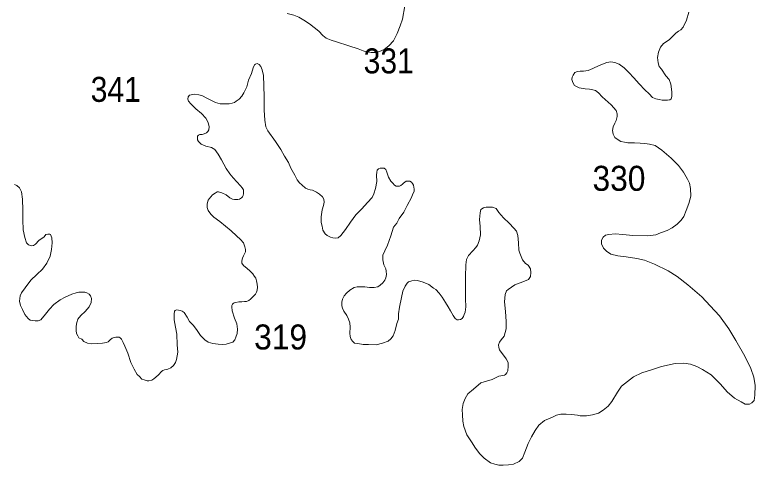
# Model space of a CAD drawing. Extents: x 445.4 to 500, y 8728.7 to 8784.
# Drawn here: x 467.934 to 472.675, y 8746.885 to 8749.766 of the extents above; entities that cross this region are included whole.
import ezdxf

# ---------------------------------------------------------------- set-up
doc = ezdxf.new("R2010")
doc.units = 0
doc.header["$LTSCALE"] = 0.064
doc.layers.add('2', color=7, linetype='Continuous', lineweight=13)
doc.layers.add('21', color=7, linetype='Continuous')

msp = doc.modelspace()

# ---------------------------------------------------------------- linework, layer by layer
at = {"layer": '2'}
for points in [[(470.4322, 8749.824), (470.4166, 8749.7394), (470.4024, 8749.6969), (470.3825, 8749.6459), (470.3584, 8749.5991), (470.33, 8749.5679), (470.2988, 8749.5439), (470.2689, 8749.5311), (470.242, 8749.5254), (470.2307, 8749.5259), (470.2165, 8749.5264), (470.2047, 8749.5278), (470.1859, 8749.5302), (470.1656, 8749.5358), (470.1321, 8749.5481), (470.0726, 8749.5674), (469.9943, 8749.5929), (469.9588, 8749.6042), (469.9276, 8749.617), (469.9063, 8749.634), (469.8807, 8749.6609), (469.8211, 8749.7077), (469.7852, 8749.7324), (469.7525, 8749.7508), (469.7199, 8749.7636), (469.6787, 8749.7749)], [(471.6363, 8749.4234), (471.6761, 8749.4432), (471.7258, 8749.4617), (471.7513, 8749.4659), (471.7769, 8749.4617), (471.8038, 8749.4503), (471.8365, 8749.4277), (471.8663, 8749.3979), (471.8975, 8749.3625), (471.9316, 8749.3256), (471.9685, 8749.2874), (471.9969, 8749.2604), (472.0182, 8749.2378), (472.0395, 8749.2293), (472.0608, 8749.2236), (472.0793, 8749.2208), (472.102, 8749.2194), (472.1134, 8749.2194), (472.1276, 8749.2222), (472.1361, 8749.2293), (472.1417, 8749.2434), (472.1417, 8749.2732), (472.1347, 8749.3228), (472.1247, 8749.3526), (472.102, 8749.3766), (472.075, 8749.4192), (472.0608, 8749.4362), (472.0537, 8749.4588), (472.0485, 8749.4937), (472.0556, 8749.5277), (472.0684, 8749.5589), (472.0869, 8749.583), (472.1238, 8749.607), (472.1437, 8749.6255), (472.1593, 8749.6411), (472.1678, 8749.6481), (472.1834, 8749.6609), (472.199, 8749.6708), (472.2146, 8749.6864), (472.2345, 8749.7332), (472.2505, 8749.7838)], [(469.1299, 8749.1353), (469.0939, 8749.1646), (469.06, 8749.1968), (469.0465, 8749.2137), (469.0408, 8749.2272), (469.0442, 8749.2407), (469.0532, 8749.2519), (469.0837, 8749.2587), (469.113, 8749.2553), (469.1355, 8749.2474), (469.1637, 8749.2339), (469.2179, 8749.2058), (469.2494, 8749.1979), (469.2742, 8749.1968), (469.3058, 8749.1979), (469.3261, 8749.2002), (469.3408, 8749.2058), (469.3521, 8749.2137), (469.3701, 8749.2272), (469.3881, 8749.2452), (469.4005, 8749.2677), (469.4186, 8749.306), (469.431, 8749.3476), (469.4495, 8749.392), (469.4608, 8749.428), (469.4687, 8749.4472), (469.4743, 8749.4517), (469.4867, 8749.4539), (469.498, 8749.4483), (469.5093, 8749.4348), (469.5172, 8749.4145), (469.5262, 8749.3785), (469.5284, 8749.3121), (469.5307, 8749.2423), (469.5308, 8749.1561), (469.5353, 8749.092), (469.5421, 8749.0492), (469.5545, 8749.0245), (469.6042, 8748.955), (469.6369, 8748.9044), (469.6605, 8748.8627), (469.6865, 8748.8222), (469.7011, 8748.7862), (469.7279, 8748.7402), (469.7412, 8748.7111), (469.7571, 8748.692), (469.7712, 8748.6787), (469.7954, 8748.6571), (469.8104, 8748.6513), (469.8245, 8748.6463), (469.8403, 8748.6455), (469.8662, 8748.6322), (469.8845, 8748.6189), (469.9036, 8748.6014), (469.9134, 8748.5871), (469.9149, 8748.5671), (469.9103, 8748.5456), (469.9026, 8748.5179), (469.8964, 8748.4749), (469.8964, 8748.438), (469.901, 8748.4134), (469.9072, 8748.3888), (469.9211, 8748.3657), (469.9349, 8748.3534), (469.955, 8748.3442), (469.9704, 8748.3396), (469.9873, 8748.3365), (470.0043, 8748.3396), (470.0212, 8748.3549), (470.0505, 8748.3918), (470.0828, 8748.4395), (470.1183, 8748.4856), (470.1552, 8748.5256), (470.1922, 8748.5656), (470.2215, 8748.5979), (470.2338, 8748.6209), (470.2446, 8748.6548), (470.2523, 8748.6994), (470.2494, 8748.7404), (470.2513, 8748.7595), (470.2552, 8748.7719), (470.2628, 8748.7814), (470.2742, 8748.7852), (470.2876, 8748.7862), (470.2981, 8748.7842), (470.3096, 8748.7776), (470.3172, 8748.7604), (470.3277, 8748.728), (470.342, 8748.7023), (470.3554, 8748.6889), (470.3659, 8748.6766), (470.3764, 8748.6708), (470.3888, 8748.6699), (470.3974, 8748.6708), (470.406, 8748.6746), (470.4156, 8748.6823), (470.4223, 8748.6899), (470.4308, 8748.6966), (470.4404, 8748.7013), (470.4509, 8748.7023), (470.4633, 8748.7013)], [(472.0106, 8747.4958), (472.0757, 8747.5166), (472.1616, 8747.5345), (472.2185, 8747.5373), (472.2614, 8747.5304), (472.3016, 8747.5166), (472.3376, 8747.4972), (472.3924, 8747.4625), (472.4534, 8747.403), (472.495, 8747.3546), (472.5435, 8747.3145), (472.5851, 8747.2896), (472.6114, 8747.2758), (472.628, 8747.2744), (472.6391, 8747.2758), (472.6544, 8747.2841), (472.6682, 8747.2993), (472.6724, 8747.3325), (472.6751, 8747.3947), (472.6654, 8747.4487), (472.6474, 8747.5026), (472.6086, 8747.5828), (472.5506, 8747.6821), (472.5063, 8747.7568), (472.4467, 8747.8397), (472.3871, 8747.9034), (472.3343, 8747.961), (472.2442, 8748.0384), (472.1749, 8748.0923), (472.1181, 8748.1283), (472.0303, 8748.1719), (471.9652, 8748.1968), (471.9167, 8748.2064), (471.8487, 8748.2189), (471.7961, 8748.2244), (471.7504, 8748.2355), (471.7226, 8748.2535), (471.7032, 8748.2728), (471.6908, 8748.3005), (471.6908, 8748.324), (471.7005, 8748.3434), (471.7157, 8748.3558), (471.7379, 8748.36), (471.7781, 8748.3641), (471.8266, 8748.36), (471.8917, 8748.3544), (471.9859, 8748.3517), (472.0386, 8748.3586), (472.0677, 8748.371), (472.1107, 8748.3862), (472.1442, 8748.4037), (472.1747, 8748.4273), (472.201, 8748.4522), (472.2177, 8748.4757), (472.2329, 8748.5144), (472.2509, 8748.56), (472.262, 8748.6057), (472.2607, 8748.6549), (472.2538, 8748.6895), (472.2413, 8748.7157), (472.2163, 8748.76), (472.1831, 8748.8015), (472.136, 8748.8499), (472.0764, 8748.8997), (472.0345, 8748.9296), (471.9985, 8748.9393), (471.968, 8748.9435), (471.9389, 8748.9462), (471.9023, 8748.9464), (471.8597, 8748.9464), (471.8384, 8748.9506), (471.8157, 8748.9563), (471.7973, 8748.9662), (471.776, 8748.9818), (471.766, 8749.003), (471.7618, 8749.0271), (471.7646, 8749.0498), (471.776, 8749.0725), (471.7845, 8749.0895), (471.7902, 8749.115), (471.7902, 8749.1334), (471.7845, 8749.1547), (471.7532, 8749.1901), (471.6959, 8749.242), (471.6718, 8749.2675), (471.6533, 8749.2817), (471.6363, 8749.2874), (471.6136, 8749.2902), (471.5866, 8749.293), (471.5483, 8749.3001), (471.5185, 8749.3143), (471.5071, 8749.3327), (471.5014, 8749.3526), (471.5028, 8749.3667), (471.5099, 8749.3809), (471.5199, 8749.3979), (471.5369, 8749.4036), (471.554, 8749.405), (471.5753, 8749.4064), (471.6065, 8749.4107), (471.6363, 8749.4234)], [(469.2612, 8747.6567), (469.2876, 8747.6598), (469.3079, 8747.666), (469.3297, 8747.6722), (469.3437, 8747.6862), (469.3484, 8747.7033), (469.3577, 8747.7282), (469.3593, 8747.7561), (469.3546, 8747.7888), (469.3406, 8747.8261), (469.3266, 8747.8727), (469.3226, 8747.8971), (469.3226, 8747.9067), (469.3271, 8747.9142), (469.3316, 8747.9187), (469.3383, 8747.9231), (469.3487, 8747.9261), (469.3682, 8747.9298), (469.3883, 8747.9306), (469.404, 8747.9313), (469.4174, 8747.9328), (469.4316, 8747.9388), (469.4428, 8747.9462), (469.4547, 8747.9574), (469.4644, 8747.9686), (469.4741, 8747.9797), (469.4808, 8747.9924), (469.4861, 8748.0051), (469.4876, 8748.0237), (469.4861, 8748.0438), (469.4808, 8748.0646), (469.4773, 8748.0808), (469.4691, 8748.0927), (469.4572, 8748.1091), (469.4408, 8748.127), (469.4191, 8748.1449), (469.4012, 8748.1612), (469.3915, 8748.1702), (469.3885, 8748.1784), (469.3885, 8748.1888), (469.39, 8748.2022), (469.3923, 8748.2104), (469.3982, 8748.2253), (469.4101, 8748.2494), (469.4112, 8748.2641), (469.4078, 8748.2809), (469.3977, 8748.3068), (469.3796, 8748.3282), (469.3537, 8748.353), (469.3187, 8748.3834), (469.2466, 8748.4441), (469.2091, 8748.4707), (469.1888, 8748.491), (469.1719, 8748.5135), (469.1662, 8748.5338), (469.1662, 8748.5563), (469.1719, 8748.5799), (469.1786, 8748.59), (469.1888, 8748.6013), (469.2001, 8748.6148), (469.217, 8748.6261), (469.2305, 8748.6328), (469.2373, 8748.6328), (469.2587, 8748.6272), (469.2869, 8748.6137), (469.3106, 8748.5957), (469.3275, 8748.5878), (469.341, 8748.5844), (469.3624, 8748.5844), (469.3737, 8748.5878), (469.3861, 8748.5946), (469.3918, 8748.6013), (469.3963, 8748.6114), (469.3985, 8748.6227), (469.3985, 8748.6362), (469.3974, 8748.6475), (469.3906, 8748.6587), (469.3794, 8748.6722), (469.3321, 8748.7225), (469.3107, 8748.7496), (469.2881, 8748.7822), (469.2566, 8748.8385), (469.2363, 8748.8756), (469.2137, 8748.9037), (469.1923, 8748.9173), (469.1573, 8748.9263), (469.1266, 8748.9384), (469.1108, 8748.9552), (469.104, 8748.9665), (469.104, 8748.989), (469.1108, 8748.9969), (469.1187, 8749.0003), (469.1333, 8749.0014), (469.1457, 8749.0048), (469.1615, 8749.0115), (469.1705, 8749.0194), (469.1773, 8749.0307), (469.1784, 8749.0487), (469.1728, 8749.0768), (469.157, 8749.1061), (469.1299, 8749.1353)], [(470.4633, 8748.7013), (470.4748, 8748.6956), (470.4815, 8748.6861), (470.4872, 8748.6756), (470.49, 8748.6632), (470.491, 8748.6508), (470.491, 8748.6365), (470.4824, 8748.6213), (470.4738, 8748.5975), (470.4473, 8748.5455), (470.4243, 8748.5045), (470.3957, 8748.4626), (470.3795, 8748.433), (470.3584, 8748.4077), (470.3416, 8748.352), (470.3212, 8748.2925), (470.3025, 8748.2553), (470.2914, 8748.2293), (470.2914, 8748.1977), (470.297, 8748.1661), (470.31, 8748.142), (470.3118, 8748.1261), (470.3147, 8748.1049), (470.3099, 8748.0845), (470.3041, 8748.0681), (470.2915, 8748.0507), (470.273, 8748.0361), (470.2585, 8748.0255), (470.2343, 8748.0216), (470.2052, 8748.0226), (470.1761, 8748.0255), (470.1489, 8748.0265), (470.1257, 8748.0265), (470.1063, 8748.0207), (470.0791, 8748.0042), (470.0578, 8747.9848), (470.0432, 8747.9674), (470.0326, 8747.9481), (470.0287, 8747.9287), (470.0287, 8747.9045), (470.0318, 8747.8884), (470.0415, 8747.87), (470.0609, 8747.8429), (470.0716, 8747.8197), (470.0784, 8747.7955), (470.0803, 8747.7684), (470.0784, 8747.7287), (470.0813, 8747.7071), (470.0881, 8747.6887), (470.0978, 8747.6771), (470.1084, 8747.6665), (470.1298, 8747.6626), (470.1647, 8747.6568), (470.1986, 8747.6568), (470.2471, 8747.6558), (470.2878, 8747.6665), (470.3237, 8747.6791), (470.3421, 8747.6936), (470.3557, 8747.7129), (470.3693, 8747.7468), (470.3809, 8747.7923), (470.3906, 8747.8184), (470.3916, 8747.8533), (470.3964, 8747.8968), (470.4093, 8747.9576), (470.419, 8747.9992), (470.4336, 8748.0292), (470.4462, 8748.0486), (470.4559, 8748.0583), (470.4753, 8748.065), (470.4908, 8748.0679), (470.5102, 8748.067), (470.5267, 8748.0621), (470.548, 8748.0554), (470.5848, 8748.0399), (470.6149, 8748.0176), (470.6304, 8748.0079), (470.6517, 8747.9857), (470.6702, 8747.9595), (470.6925, 8747.9257), (470.7099, 8747.8986), (470.7235, 8747.8734), (470.7404, 8747.8428), (470.7539, 8747.8225), (470.7665, 8747.8148), (470.7753, 8747.8138), (470.7888, 8747.8167), (470.7976, 8747.8235), (470.8063, 8747.837), (470.8121, 8747.8486), (470.817, 8747.8631), (470.8218, 8747.899), (470.8208, 8747.9502), (470.82, 8748.0891), (470.8215, 8748.1662), (470.8256, 8748.2009), (470.8399, 8748.2254), (470.8665, 8748.2561), (470.887, 8748.2785), (470.8972, 8748.2928), (470.9074, 8748.3194)], [(467.9321, 8748.6801), (467.947, 8748.6742), (467.9634, 8748.6593), (467.9769, 8748.6339), (467.9828, 8748.5863), (467.9846, 8748.5168), (467.9846, 8748.4549), (467.9877, 8748.3915), (467.997, 8748.3421), (468.0094, 8748.308), (468.0218, 8748.2957), (468.0388, 8748.2879), (468.0528, 8748.2895), (468.0667, 8748.2988), (468.0869, 8748.322), (468.1209, 8748.3467), (468.1318, 8748.3606), (468.1442, 8748.3637), (468.1581, 8748.3637), (468.1628, 8748.3606), (468.1705, 8748.3405), (468.1736, 8748.3065), (468.169, 8748.2647), (468.1612, 8748.2215), (468.138, 8748.177), (468.1116, 8748.1383), (468.0745, 8748.1043), (468.0357, 8748.0687)], [(470.9074, 8748.3194), (470.916, 8748.3594), (470.9147, 8748.4119), (470.9105, 8748.4562), (470.9133, 8748.4991), (470.9188, 8748.5212), (470.9354, 8748.5323), (470.9521, 8748.535), (470.9742, 8748.5364), (470.9936, 8748.535), (471.0158, 8748.5267), (471.0324, 8748.5018), (471.0643, 8748.4672), (471.099, 8748.4327), (471.1294, 8748.4009), (471.1461, 8748.3815), (471.1558, 8748.3538), (471.1585, 8748.3082), (471.1613, 8748.2612), (471.1686, 8748.2411), (471.1853, 8748.1996), (471.2033, 8748.1761), (471.2213, 8748.1636), (471.2352, 8748.1415), (471.2393, 8748.1166), (471.2365, 8748.0931), (471.2227, 8748.0737), (471.1866, 8748.0585), (471.1368, 8748.0378), (471.0924, 8748.0087), (471.0826, 8747.9996), (471.0729, 8747.9775), (471.0702, 8747.9291), (471.0757, 8747.8682), (471.0813, 8747.8046), (471.0798, 8747.7582), (471.0743, 8747.7347), (471.0674, 8747.7112), (471.048, 8747.6863), (471.0369, 8747.6724), (471.0313, 8747.6558), (471.0327, 8747.6379), (471.0383, 8747.6226), (471.048, 8747.6088), (471.0632, 8747.5881), (471.0798, 8747.5645), (471.0923, 8747.5424), (471.0937, 8747.5175), (471.0909, 8747.4878), (471.0854, 8747.4754), (471.0771, 8747.4643), (471.0701, 8747.4602), (471.0327, 8747.4533), (470.9898, 8747.4339), (470.9191, 8747.4118), (470.8706, 8747.3717), (470.8359, 8747.3412), (470.8177, 8747.3116), (470.8052, 8747.2784), (470.7983, 8747.241), (470.7997, 8747.2078), (470.8024, 8747.1663), (470.8093, 8747.1323), (470.8287, 8747.0798), (470.8578, 8747.0341), (470.8841, 8746.9926), (470.9119, 8746.9581), (470.9396, 8746.929), (470.9811, 8746.9), (471.0075, 8746.8917), (471.0338, 8746.8848), (471.0601, 8746.8848), (471.0948, 8746.8861), (471.128, 8746.8917), (471.1641, 8746.9083), (471.1849, 8746.9304), (471.2001, 8746.9677), (471.2209, 8747.0244), (471.2417, 8747.0659), (471.2666, 8747.1074), (471.2888, 8747.1406), (471.3262, 8747.1697), (471.3775, 8747.1918), (471.4018, 8747.2058), (471.4295, 8747.2113), (471.4656, 8747.2113), (471.4988, 8747.2085), (471.5362, 8747.2044), (471.5542, 8747.2002), (471.5958, 8747.2016), (471.6332, 8747.2071), (471.6707, 8747.2182), (471.7025, 8747.2362), (471.733, 8747.2625), (471.7566, 8747.2915), (471.793, 8747.352), (471.8193, 8747.3893), (471.8568, 8747.4211), (471.8956, 8747.4502), (471.9496, 8747.4765), (472.0106, 8747.4958)], [(468.0357, 8748.0687), (468.0001, 8748.0193), (467.9769, 8747.9883), (467.9676, 8747.9682), (467.9645, 8747.9342), (467.9707, 8747.9064), (467.9831, 8747.8801), (467.9986, 8747.8492), (468.0188, 8747.8223), (468.0327, 8747.813), (468.0467, 8747.8099), (468.0637, 8747.8084), (468.0839, 8747.8084), (468.1009, 8747.8146), (468.1303, 8747.8501), (468.1567, 8747.8826), (468.1846, 8747.912), (468.2233, 8747.9429), (468.2558, 8747.9599), (468.2992, 8747.9785), (468.3271, 8747.9877), (468.3441, 8747.9924), (468.3596, 8747.9924), (468.3828, 8747.9908), (468.3952, 8747.9877), (468.4092, 8747.98), (468.4185, 8747.9676), (468.4247, 8747.9522), (468.4231, 8747.9259), (468.4107, 8747.8981), (468.3844, 8747.8671), (468.3565, 8747.8424), (468.3364, 8747.8192), (468.3302, 8747.7976), (468.3271, 8747.7744), (468.3271, 8747.7465), (468.3286, 8747.728), (468.3364, 8747.7125), (468.3441, 8747.7002), (468.3627, 8747.6909), (468.3766, 8747.677), (468.3983, 8747.6646), (468.4231, 8747.6615), (468.4649, 8747.6631), (468.4959, 8747.6646), (468.52, 8747.6689), (468.5306, 8747.6748), (468.5447, 8747.6871), (468.5577, 8747.6971), (468.5706, 8747.7018), (468.58, 8747.7036), (468.5912, 8747.7048), (468.6012, 8747.703), (468.6089, 8747.7001), (468.6177, 8747.6907), (468.6283, 8747.6707), (468.6389, 8747.6466), (468.6577, 8747.6006), (468.6778, 8747.5418), (468.698, 8747.5001), (468.7166, 8747.4645), (468.7323, 8747.4516), (468.7462, 8747.4361), (468.7632, 8747.4299), (468.7803, 8747.4253), (468.7927, 8747.4253), (468.8117, 8747.4297), (468.823, 8747.4367), (468.8377, 8747.4472), (468.8539, 8747.4634), (468.8729, 8747.4844), (468.8827, 8747.4914), (468.8919, 8747.4942), (468.9129, 8747.4992), (468.9326, 8747.5076), (468.9495, 8747.5216), (468.9635, 8747.5412), (468.9699, 8747.5602), (468.977, 8747.607), (468.9739, 8747.655), (468.9708, 8747.723), (468.9631, 8747.7678), (468.9553, 8747.8142), (468.9553, 8747.8508), (468.957, 8747.8702), (468.9604, 8747.8744), (468.9689, 8747.8778), (468.9824, 8747.8761), (468.9943, 8747.8753), (469.0061, 8747.871), (469.018, 8747.8609), (469.0366, 8747.8313), (469.0527, 8747.8052), (469.0789, 8747.7781), (469.1026, 8747.7469), (469.1229, 8747.7139), (469.1506, 8747.6877), (469.1724, 8747.6722), (469.202, 8747.6629), (469.2362, 8747.6582), (469.2612, 8747.6567)]]:
    msp.add_lwpolyline(points, dxfattribs=at)

# ---------------------------------------------------------------- texts
at = {"layer": '21'}
for s, width, p in [('331', 0.9, (470.1676, 8749.3916)), ('341', 0.9, (468.4197, 8749.2095)), ('330', 0.95, (471.6333, 8748.6403)), ('319', 0.95, (469.4663, 8747.6251))]:
    msp.add_text(s, height=0.16, dxfattribs=dict(at, width=width)).set_placement(p)

doc.saveas('drawing.dxf')
